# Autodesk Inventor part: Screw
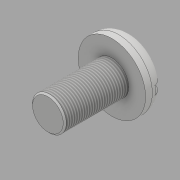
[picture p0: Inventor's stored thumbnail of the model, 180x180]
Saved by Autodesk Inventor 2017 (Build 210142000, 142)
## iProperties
Created: 2016-05
Part Number: Screw
Material: Generic
Document SubType Name: Modeling
Designer: CADCIM
Density: 1 g/cm^3
Appearance: Default
Author: CADCIM
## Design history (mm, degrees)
sketch "Sketch1"
  geometry: C1 r 20 at (0, 0); 1 further point
  constraints: 1 centre point, 1 coincident
  dimensions: "d0" = 40 diameter of C1
extrude "Extrusion1" new body sketch "Sketch1" distance "d1" = 12; taper "d2" = 0 deg
fillet "Fillet1" dims "d3" = 8
sketch "Sketch2"
  geometry: C1 r 10 at (0, 0); 1 further point
  constraints: 1 centre point, 1 coincident
  dimensions: "d4" = 20 diameter of C1
extrude "Extrusion2" join sketch "Sketch2" distance "d5" = 38; taper "d6" = 0 deg
sketch "Sketch3"
  geometry: L1 (-25.5, -2.5)-(23.9, -2.5); L2 (23.9, -2.5)-(23.9, 2.5); L3 (23.9, 2.5)-(-25.5, 2.5); L4 (-25.5, 2.5)-(-25.5, -2.5); L5 (0, 0)-(-30.181, 0)
  constraints: 10 end point, 2 horizontal, 2 parallel, 1 perpendicular, 1 other
  dimensions: "d7" = 5 distance of L3.end L1.start
extrude "Extrusion3" cut sketch "Sketch3" distance "d8" = 6; taper "d9" = 0 deg
thread "Thread1" dims "d10" = 10, "d11" = 0
chamfer "Chamfer1" distance "d12" = 0.9; stored, may be unused: second distance "d13" = 2, angle "d14" = 45 deg
body "Solid1"
